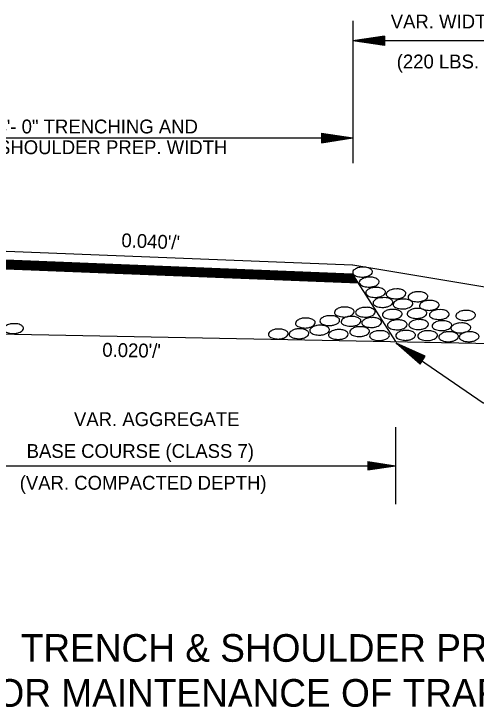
# Model space of a CAD drawing. Extents: x 1929624 to 1936506, y 596315 to 605721.
# Drawn here: x 1933894.6 to 1934095, y 603512.5 to 603813.2 of the extents above; entities that cross this region are included whole.
import ezdxf

# ---------------------------------------------------------------- set-up
doc = ezdxf.new("R2010")
doc.units = 0
doc.layers.add('Default', color=7, linetype='Continuous')
doc.layers.add('R_Border', color=7, linetype='Continuous')

msp = doc.modelspace()

# ---------------------------------------------------------------- linework, layer by layer
at = {"layer": 'Default'}
for p, q in [((1934041.58, 603810.24), (1934041.58, 603748.47)), ((1934055.28, 603803.61), (1934041.58, 603801.57)), ((1934055.28, 603803.28), (1934043.85, 603801.57)), ((1934055.28, 603803.61), (1934055.28, 603799.51)), ((1934055.28, 603799.51), (1934041.58, 603801.57)), ((1934282.32, 603801.57), (1934041.58, 603801.57)), ((1934055.28, 603799.86), (1934043.85, 603801.57)), ((1934055.28, 603802.93), (1934046.22, 603801.57)), ((1934055.28, 603800.2), (1934046.22, 603801.57)), ((1934055.28, 603802.6), (1934048.5, 603801.57)), ((1934055.28, 603800.56), (1934048.5, 603801.57)), ((1934055.28, 603802.21), (1934050.82, 603801.57)), ((1934055.28, 603800.89), (1934050.82, 603801.57)), ((1934055.28, 603801.9), (1934053.09, 603801.57)), ((1934055.28, 603801.24), (1934053.09, 603801.57)), ((1934027.9, 603761.42), (1934041.58, 603759.38)), ((1934027.9, 603761.42), (1934027.9, 603757.32)), ((1934027.9, 603761.09), (1934039.29, 603759.38)), ((1933862.89, 603759.38), (1934041.58, 603759.38)), ((1934027.9, 603760.73), (1934036.95, 603759.38)), ((1934027.9, 603760.4), (1934034.68, 603759.38)), ((1934027.9, 603760.03), (1934032.32, 603759.38)), ((1934027.9, 603759.7), (1934030.05, 603759.38)), ((1934027.9, 603757.32), (1934041.58, 603759.38)), ((1934027.9, 603758.69), (1934032.32, 603759.38)), ((1934027.9, 603758), (1934036.95, 603759.38)), ((1934027.9, 603757.66), (1934039.29, 603759.38)), ((1934027.9, 603758.36), (1934034.68, 603759.38)), ((1934027.9, 603759.05), (1934030.05, 603759.38)), ((1934041.58, 603755.33), (1934041.58, 603748.47)), ((1933859.07, 603711.63), (1934041.46, 603704.32)), ((1933859.07, 603707.83), (1934041.3, 603700.5)), ((1933859.07, 603707.39), (1934041.58, 603700.05)), ((1933859.07, 603707.06), (1934041.77, 603699.76)), ((1933859.07, 603706.64), (1934042.08, 603699.3)), ((1933859.07, 603706.22), (1934042.3, 603698.9)), ((1933859.07, 603705.86), (1934042.58, 603698.46)), ((1933859.07, 603705.48), (1934042.8, 603698.12)), ((1933859.07, 603705.1), (1934043.12, 603697.68)), ((1933859.07, 603704.68), (1934043.36, 603697.28)), ((1933859.07, 603704.31), (1934043.62, 603696.84)), ((1933859.07, 603703.98), (1934043.79, 603696.56)), ((1934041.58, 603704.32), (1934432.81, 603639.11)), ((1934041.3, 603700.5), (1934060, 603671.04)), ((1933862.98, 603674.97), (1934265.9, 603666.92)), ((1934070.71, 603661.22), (1934060.36, 603670.42)), ((1934072.95, 603664.68), (1934060.36, 603670.42)), ((1934070.9, 603661.49), (1934062.29, 603669.18)), ((1934072.78, 603664.36), (1934062.29, 603669.18)), ((1934072.58, 603664.09), (1934064.27, 603667.88)), ((1934071.1, 603661.8), (1934064.27, 603667.88)), ((1934071.29, 603662.09), (1934066.17, 603666.63)), ((1934072.39, 603663.78), (1934066.17, 603666.63)), ((1934072.2, 603663.5), (1934068.12, 603665.38)), ((1934071.47, 603662.4), (1934068.12, 603665.38)), ((1934070.71, 603661.22), (1934072.95, 603664.68)), ((1934072.01, 603663.2), (1934070.03, 603664.14)), ((1934071.67, 603662.66), (1934070.03, 603664.14)), ((1934060, 603633.89), (1934060, 603600.53)), ((1933862.98, 603617.21), (1934060, 603617.21)), ((1934048, 603619.01), (1934060, 603617.21)), ((1934048, 603619.01), (1934048, 603615.41)), ((1934048, 603618.71), (1934058, 603617.21)), ((1934048, 603618.4), (1934055.93, 603617.21)), ((1934048, 603618.1), (1934053.93, 603617.21)), ((1934048, 603617.79), (1934051.9, 603617.21)), ((1934048, 603617.49), (1934049.9, 603617.21)), ((1934048, 603615.41), (1934060, 603617.21)), ((1934048, 603616.62), (1934051.9, 603617.21)), ((1934048, 603616.02), (1934055.93, 603617.21)), ((1934048, 603615.71), (1934058, 603617.21)), ((1934048, 603616.32), (1934053.93, 603617.21)), ((1934048, 603616.93), (1934049.9, 603617.21))]:
    msp.add_line(p, q, dxfattribs=at)
for points in [[(1934045.68, 603703.29), (1934047.21, 603703.28), (1934049.03, 603702.64), (1934049.92, 603701.81), (1934050.04, 603701.27), (1934049.58, 603700.35), (1934049.06, 603699.96), (1934048.06, 603699.44), (1934046.6, 603699.1), (1934045.84, 603699.02), (1934044.73, 603699.13), (1934043.47, 603699.34), (1934042.52, 603699.71), (1934041.64, 603700.44), (1934041.49, 603701.02), (1934041.75, 603701.84), (1934042.45, 603702.37), (1934043.09, 603702.79), (1934044.11, 603703.14), (1934044.74, 603703.28), (1934045.68, 603703.29)], [(1934048.56, 603698.96), (1934050.06, 603698.95), (1934051.88, 603698.31), (1934052.8, 603697.47), (1934052.93, 603696.94), (1934052.44, 603696.02), (1934051.9, 603695.6), (1934050.95, 603695.1), (1934049.43, 603694.79), (1934048.7, 603694.68), (1934047.56, 603694.8), (1934046.35, 603695), (1934045.41, 603695.39), (1934044.51, 603696.08), (1934044.35, 603696.69), (1934044.64, 603697.5), (1934045.32, 603698.06), (1934045.98, 603698.48), (1934046.96, 603698.79), (1934047.58, 603698.95), (1934048.56, 603698.96)], [(1934051.32, 603694.49), (1934052.83, 603694.47), (1934054.64, 603693.85), (1934055.54, 603692.98), (1934055.7, 603692.48), (1934055.22, 603691.54), (1934054.69, 603691.12), (1934053.7, 603690.67), (1934052.22, 603690.28), (1934051.46, 603690.22), (1934050.34, 603690.3), (1934049.11, 603690.52), (1934048.16, 603690.9), (1934047.28, 603691.61), (1934047.13, 603692.21), (1934047.39, 603693.01), (1934048.08, 603693.59), (1934048.72, 603694.02), (1934049.75, 603694.33), (1934050.37, 603694.47), (1934051.32, 603694.49)], [(1934060.22, 603693.87), (1934061.73, 603693.85), (1934063.54, 603693.23), (1934064.46, 603692.35), (1934064.57, 603691.87), (1934064.11, 603690.92), (1934063.58, 603690.52), (1934062.6, 603690.03), (1934061.11, 603689.66), (1934060.36, 603689.6), (1934059.24, 603689.71), (1934058.01, 603689.91), (1934057.04, 603690.28), (1934056.17, 603691.01), (1934056.01, 603691.59), (1934056.28, 603692.4), (1934056.98, 603692.96), (1934057.62, 603693.38), (1934058.64, 603693.71), (1934059.25, 603693.85), (1934060.22, 603693.87)], [(1934069.68, 603692.6), (1934071.19, 603692.59), (1934073.03, 603691.98), (1934073.92, 603691.11), (1934074.06, 603690.62), (1934073.57, 603689.66), (1934073.04, 603689.25), (1934072.05, 603688.8), (1934070.57, 603688.43), (1934069.83, 603688.36), (1934068.7, 603688.44), (1934067.46, 603688.65), (1934066.53, 603689.03), (1934065.61, 603689.75), (1934065.5, 603690.33), (1934065.77, 603691.14), (1934066.44, 603691.7), (1934067.09, 603692.14), (1934068.09, 603692.46), (1934068.73, 603692.59), (1934069.68, 603692.6)], [(1934054.53, 603690.11), (1934056.01, 603690.09), (1934057.85, 603689.5), (1934058.72, 603688.63), (1934058.88, 603688.13), (1934058.41, 603687.18), (1934057.87, 603686.78), (1934056.88, 603686.31), (1934055.42, 603685.93), (1934054.64, 603685.87), (1934053.53, 603685.95), (1934052.3, 603686.15), (1934051.35, 603686.56), (1934050.45, 603687.27), (1934050.32, 603687.84), (1934050.59, 603688.66), (1934051.27, 603689.21), (1934051.9, 603689.64), (1934052.93, 603689.99), (1934053.55, 603690.09), (1934054.53, 603690.11)], [(1934063.24, 603689.47), (1934064.72, 603689.46), (1934066.56, 603688.83), (1934067.43, 603687.96), (1934067.59, 603687.46), (1934067.12, 603686.53), (1934066.58, 603686.12), (1934065.59, 603685.64), (1934064.13, 603685.26), (1934063.35, 603685.22), (1934062.26, 603685.28), (1934061.01, 603685.48), (1934060.06, 603685.89), (1934059.17, 603686.59), (1934059.03, 603687.18), (1934059.31, 603688.01), (1934060, 603688.57), (1934060.61, 603689), (1934061.64, 603689.3), (1934062.28, 603689.46), (1934063.24, 603689.47)], [(1934074.65, 603688.86), (1934076.14, 603688.85), (1934077.95, 603688.22), (1934078.86, 603687.35), (1934079.01, 603686.87), (1934078.53, 603685.93), (1934077.98, 603685.5), (1934077, 603685.05), (1934075.52, 603684.69), (1934074.77, 603684.61), (1934073.68, 603684.7), (1934072.42, 603684.91), (1934071.48, 603685.28), (1934070.57, 603685.98), (1934070.44, 603686.59), (1934070.72, 603687.41), (1934071.41, 603687.96), (1934072.03, 603688.4), (1934073.04, 603688.69), (1934073.7, 603688.85), (1934074.65, 603688.86)], [(1934037.8, 603686), (1934039.33, 603685.99), (1934041.15, 603685.35), (1934042.04, 603684.52), (1934042.16, 603683.98), (1934041.7, 603683.06), (1934041.18, 603682.67), (1934040.18, 603682.15), (1934038.72, 603681.81), (1934037.96, 603681.73), (1934036.85, 603681.84), (1934035.59, 603682.05), (1934034.64, 603682.42), (1934033.76, 603683.15), (1934033.61, 603683.73), (1934033.87, 603684.55), (1934034.57, 603685.08), (1934035.21, 603685.5), (1934036.23, 603685.85), (1934036.86, 603685.99), (1934037.8, 603686)], [(1934046.93, 603685.9), (1934048.46, 603685.89), (1934050.28, 603685.25), (1934051.17, 603684.42), (1934051.29, 603683.88), (1934050.83, 603682.96), (1934050.31, 603682.57), (1934049.31, 603682.05), (1934047.85, 603681.71), (1934047.09, 603681.63), (1934045.98, 603681.74), (1934044.72, 603681.95), (1934043.77, 603682.32), (1934042.89, 603683.05), (1934042.74, 603683.63), (1934043, 603684.45), (1934043.7, 603684.98), (1934044.34, 603685.4), (1934045.36, 603685.75), (1934045.99, 603685.89), (1934046.93, 603685.9)], [(1934058.55, 603685.01), (1934060.09, 603684.97), (1934061.92, 603684.36), (1934062.81, 603683.49), (1934062.91, 603682.99), (1934062.45, 603682.04), (1934061.93, 603681.63), (1934060.95, 603681.15), (1934059.47, 603680.79), (1934058.71, 603680.73), (1934057.6, 603680.82), (1934056.38, 603681.04), (1934055.42, 603681.41), (1934054.53, 603682.12), (1934054.37, 603682.72), (1934054.64, 603683.55), (1934055.33, 603684.08), (1934055.98, 603684.52), (1934056.98, 603684.84), (1934057.62, 603684.97), (1934058.55, 603685.01)], [(1934069.29, 603685.39), (1934070.8, 603685.37), (1934072.62, 603684.73), (1934073.54, 603683.88), (1934073.68, 603683.38), (1934073.18, 603682.44), (1934072.65, 603682.02), (1934071.69, 603681.54), (1934070.18, 603681.17), (1934069.44, 603681.12), (1934068.31, 603681.2), (1934067.09, 603681.41), (1934066.14, 603681.8), (1934065.25, 603682.51), (1934065.11, 603683.13), (1934065.38, 603683.91), (1934066.06, 603684.47), (1934066.72, 603684.91), (1934067.7, 603685.23), (1934068.32, 603685.37), (1934069.29, 603685.39)], [(1934078.95, 603684.91), (1934080.43, 603684.89), (1934082.27, 603684.27), (1934083.16, 603683.39), (1934083.31, 603682.88), (1934082.81, 603681.98), (1934082.28, 603681.54), (1934081.3, 603681.09), (1934079.81, 603680.7), (1934079.06, 603680.65), (1934077.94, 603680.73), (1934076.72, 603680.93), (1934075.77, 603681.32), (1934074.87, 603682.02), (1934074.73, 603682.63), (1934075.01, 603683.43), (1934075.68, 603684), (1934076.33, 603684.44), (1934077.34, 603684.73), (1934077.95, 603684.89), (1934078.95, 603684.91)], [(1934090.4, 603684.52), (1934091.91, 603684.5), (1934093.75, 603683.88), (1934094.63, 603683), (1934094.75, 603682.51), (1934094.3, 603681.59), (1934093.77, 603681.15), (1934092.77, 603680.68), (1934091.29, 603680.32), (1934090.56, 603680.25), (1934089.42, 603680.34), (1934088.17, 603680.54), (1934087.25, 603680.93), (1934086.34, 603681.63), (1934086.21, 603682.23), (1934086.49, 603683.05), (1934087.16, 603683.6), (1934087.8, 603684.05), (1934088.81, 603684.36), (1934089.45, 603684.5), (1934090.4, 603684.52)], [(1934020.9, 603681.23), (1934022.43, 603681.22), (1934024.25, 603680.58), (1934025.14, 603679.75), (1934025.26, 603679.21), (1934024.8, 603678.29), (1934024.28, 603677.9), (1934023.28, 603677.38), (1934021.82, 603677.04), (1934021.06, 603676.96), (1934019.95, 603677.07), (1934018.69, 603677.28), (1934017.74, 603677.65), (1934016.86, 603678.38), (1934016.71, 603678.96), (1934016.97, 603679.78), (1934017.67, 603680.31), (1934018.31, 603680.73), (1934019.33, 603681.08), (1934019.96, 603681.22), (1934020.9, 603681.23)], [(1934031.47, 603682.27), (1934033, 603682.26), (1934034.82, 603681.62), (1934035.71, 603680.79), (1934035.83, 603680.25), (1934035.37, 603679.33), (1934034.85, 603678.94), (1934033.85, 603678.42), (1934032.39, 603678.08), (1934031.63, 603678), (1934030.52, 603678.11), (1934029.26, 603678.32), (1934028.31, 603678.69), (1934027.43, 603679.42), (1934027.28, 603680), (1934027.54, 603680.82), (1934028.24, 603681.35), (1934028.88, 603681.77), (1934029.9, 603682.12), (1934030.53, 603682.26), (1934031.47, 603682.27)], [(1934040.7, 603681.96), (1934042.23, 603681.95), (1934044.05, 603681.31), (1934044.94, 603680.48), (1934045.06, 603679.94), (1934044.6, 603679.02), (1934044.08, 603678.63), (1934043.08, 603678.11), (1934041.62, 603677.77), (1934040.86, 603677.69), (1934039.75, 603677.8), (1934038.49, 603678.01), (1934037.54, 603678.38), (1934036.66, 603679.11), (1934036.51, 603679.69), (1934036.77, 603680.51), (1934037.47, 603681.04), (1934038.11, 603681.46), (1934039.13, 603681.81), (1934039.76, 603681.95), (1934040.7, 603681.96)], [(1934049.62, 603681.44), (1934051.15, 603681.43), (1934052.97, 603680.79), (1934053.86, 603679.96), (1934053.98, 603679.42), (1934053.52, 603678.5), (1934053, 603678.11), (1934052, 603677.59), (1934050.54, 603677.25), (1934049.78, 603677.17), (1934048.67, 603677.28), (1934047.41, 603677.49), (1934046.46, 603677.86), (1934045.58, 603678.59), (1934045.43, 603679.17), (1934045.69, 603679.99), (1934046.39, 603680.52), (1934047.03, 603680.94), (1934048.05, 603681.29), (1934048.68, 603681.43), (1934049.62, 603681.44)], [(1934060.72, 603680.45), (1934062.26, 603680.4), (1934064.08, 603679.79), (1934064.97, 603678.92), (1934065.08, 603678.42), (1934064.61, 603677.47), (1934064.1, 603677.07), (1934063.12, 603676.58), (1934061.64, 603676.23), (1934060.87, 603676.16), (1934059.77, 603676.26), (1934058.55, 603676.48), (1934057.58, 603676.85), (1934056.7, 603677.55), (1934056.54, 603678.16), (1934056.81, 603678.98), (1934057.49, 603679.51), (1934058.15, 603679.95), (1934059.14, 603680.28), (1934059.78, 603680.4), (1934060.72, 603680.45)], [(1934070, 603680.57), (1934071.52, 603680.56), (1934073.34, 603679.92), (1934074.26, 603679.06), (1934074.4, 603678.56), (1934073.9, 603677.63), (1934073.37, 603677.21), (1934072.4, 603676.72), (1934070.89, 603676.35), (1934070.16, 603676.3), (1934069.02, 603676.38), (1934067.81, 603676.6), (1934066.86, 603676.99), (1934065.97, 603677.69), (1934065.83, 603678.31), (1934066.09, 603679.09), (1934066.78, 603679.65), (1934067.43, 603680.09), (1934068.41, 603680.42), (1934069.04, 603680.56), (1934070, 603680.57)], [(1934080.1, 603680.09), (1934081.61, 603680.07), (1934083.44, 603679.44), (1934084.36, 603678.58), (1934084.5, 603678.08), (1934084, 603677.15), (1934083.47, 603676.72), (1934082.5, 603676.24), (1934080.99, 603675.87), (1934080.26, 603675.82), (1934079.12, 603675.9), (1934077.91, 603676.12), (1934076.95, 603676.51), (1934076.07, 603677.21), (1934075.93, 603677.83), (1934076.19, 603678.61), (1934076.88, 603679.17), (1934077.53, 603679.61), (1934078.51, 603679.93), (1934079.14, 603680.07), (1934080.1, 603680.09)], [(1933894.39, 603678.8), (1933895.92, 603678.79), (1933897.74, 603678.15), (1933898.63, 603677.32), (1933898.75, 603676.78), (1933898.29, 603675.86), (1933897.77, 603675.47), (1933896.77, 603674.95), (1933895.31, 603674.61), (1933894.55, 603674.53), (1933893.44, 603674.64), (1933892.18, 603674.85), (1933891.23, 603675.22), (1933890.35, 603675.95), (1933890.2, 603676.53), (1933890.46, 603677.35), (1933891.16, 603677.88), (1933891.8, 603678.3), (1933892.82, 603678.65), (1933893.45, 603678.79), (1933894.39, 603678.8)], [(1934027.07, 603678.12), (1934028.6, 603678.11), (1934030.42, 603677.47), (1934031.31, 603676.64), (1934031.43, 603676.1), (1934030.97, 603675.18), (1934030.45, 603674.79), (1934029.45, 603674.27), (1934027.99, 603673.93), (1934027.23, 603673.85), (1934026.12, 603673.96), (1934024.86, 603674.17), (1934023.91, 603674.54), (1934023.03, 603675.27), (1934022.88, 603675.85), (1934023.14, 603676.67), (1934023.84, 603677.2), (1934024.48, 603677.62), (1934025.5, 603677.97), (1934026.13, 603678.11), (1934027.07, 603678.12)], [(1934044.42, 603677.49), (1934045.95, 603677.48), (1934047.77, 603676.84), (1934048.66, 603676.01), (1934048.78, 603675.47), (1934048.32, 603674.55), (1934047.8, 603674.16), (1934046.8, 603673.64), (1934045.34, 603673.3), (1934044.58, 603673.22), (1934043.47, 603673.33), (1934042.21, 603673.54), (1934041.26, 603673.91), (1934040.38, 603674.64), (1934040.23, 603675.22), (1934040.49, 603676.04), (1934041.19, 603676.57), (1934041.83, 603676.99), (1934042.85, 603677.34), (1934043.48, 603677.48), (1934044.42, 603677.49)], [(1934088.27, 603679.12), (1934089.78, 603679.11), (1934091.6, 603678.47), (1934092.52, 603677.61), (1934092.66, 603677.11), (1934092.16, 603676.18), (1934091.63, 603675.76), (1934090.67, 603675.28), (1934089.16, 603674.9), (1934088.42, 603674.85), (1934087.29, 603674.93), (1934086.07, 603675.15), (1934085.12, 603675.54), (1934084.23, 603676.24), (1934084.09, 603676.86), (1934084.36, 603677.64), (1934085.04, 603678.2), (1934085.7, 603678.64), (1934086.68, 603678.97), (1934087.3, 603679.11), (1934088.27, 603679.12)], [(1934009.18, 603676.46), (1934010.71, 603676.45), (1934012.53, 603675.81), (1934013.42, 603674.98), (1934013.54, 603674.44), (1934013.08, 603673.52), (1934012.56, 603673.13), (1934011.56, 603672.61), (1934010.1, 603672.27), (1934009.34, 603672.19), (1934008.23, 603672.3), (1934006.97, 603672.51), (1934006.02, 603672.88), (1934005.14, 603673.61), (1934004.99, 603674.19), (1934005.25, 603675.01), (1934005.95, 603675.54), (1934006.59, 603675.96), (1934007.61, 603676.31), (1934008.24, 603676.45), (1934009.18, 603676.46)], [(1934018.16, 603676.56), (1934019.69, 603676.55), (1934021.51, 603675.91), (1934022.4, 603675.08), (1934022.52, 603674.54), (1934022.06, 603673.62), (1934021.54, 603673.23), (1934020.54, 603672.71), (1934019.08, 603672.37), (1934018.32, 603672.29), (1934017.21, 603672.4), (1934015.95, 603672.61), (1934015, 603672.98), (1934014.12, 603673.71), (1934013.97, 603674.29), (1934014.23, 603675.11), (1934014.93, 603675.64), (1934015.57, 603676.06), (1934016.59, 603676.41), (1934017.22, 603676.55), (1934018.16, 603676.56)], [(1934035.2, 603676.24), (1934036.73, 603676.23), (1934038.55, 603675.59), (1934039.44, 603674.76), (1934039.56, 603674.22), (1934039.1, 603673.3), (1934038.58, 603672.91), (1934037.58, 603672.39), (1934036.12, 603672.05), (1934035.36, 603671.97), (1934034.25, 603672.08), (1934032.99, 603672.29), (1934032.04, 603672.66), (1934031.16, 603673.39), (1934031.01, 603673.97), (1934031.27, 603674.79), (1934031.97, 603675.32), (1934032.61, 603675.74), (1934033.63, 603676.09), (1934034.26, 603676.23), (1934035.2, 603676.24)], [(1934053.01, 603675.77), (1934054.54, 603675.76), (1934056.36, 603675.12), (1934057.25, 603674.29), (1934057.37, 603673.75), (1934056.91, 603672.83), (1934056.39, 603672.44), (1934055.39, 603671.92), (1934053.93, 603671.58), (1934053.17, 603671.5), (1934052.06, 603671.61), (1934050.8, 603671.82), (1934049.85, 603672.19), (1934048.97, 603672.92), (1934048.82, 603673.5), (1934049.08, 603674.32), (1934049.78, 603674.85), (1934050.42, 603675.27), (1934051.44, 603675.62), (1934052.07, 603675.76), (1934053.01, 603675.77)], [(1934064.32, 603675.88), (1934065.86, 603675.84), (1934067.68, 603675.23), (1934068.57, 603674.36), (1934068.68, 603673.86), (1934068.21, 603672.91), (1934067.7, 603672.5), (1934066.72, 603672.02), (1934065.24, 603671.66), (1934064.47, 603671.6), (1934063.37, 603671.69), (1934062.15, 603671.91), (1934061.18, 603672.28), (1934060.3, 603672.98), (1934060.14, 603673.59), (1934060.41, 603674.42), (1934061.09, 603674.95), (1934061.75, 603675.38), (1934062.74, 603675.71), (1934063.38, 603675.84), (1934064.32, 603675.88)], [(1934073.85, 603675.76), (1934075.37, 603675.74), (1934077.19, 603675.1), (1934078.11, 603674.25), (1934078.25, 603673.75), (1934077.75, 603672.81), (1934077.22, 603672.39), (1934076.25, 603671.91), (1934074.74, 603671.54), (1934074.01, 603671.49), (1934072.87, 603671.57), (1934071.66, 603671.78), (1934070.71, 603672.17), (1934069.82, 603672.88), (1934069.68, 603673.5), (1934069.94, 603674.28), (1934070.63, 603674.84), (1934071.28, 603675.28), (1934072.26, 603675.6), (1934072.89, 603675.74), (1934073.85, 603675.76)], [(1934082.99, 603675.28), (1934084.5, 603675.26), (1934086.32, 603674.62), (1934087.24, 603673.76), (1934087.38, 603673.26), (1934086.88, 603672.33), (1934086.35, 603671.91), (1934085.38, 603671.43), (1934083.87, 603671.05), (1934083.14, 603671.01), (1934082, 603671.08), (1934080.79, 603671.3), (1934079.84, 603671.69), (1934078.95, 603672.39), (1934078.81, 603673.02), (1934079.07, 603673.79), (1934079.76, 603674.36), (1934080.41, 603674.79), (1934081.4, 603675.12), (1934082.02, 603675.26), (1934082.99, 603675.28)], [(1934091.87, 603675.28), (1934093.38, 603675.26), (1934095.2, 603674.62), (1934096.12, 603673.76), (1934096.26, 603673.26), (1934095.76, 603672.33), (1934095.23, 603671.91), (1934094.27, 603671.43), (1934092.76, 603671.05), (1934092.02, 603671.01), (1934090.89, 603671.08), (1934089.67, 603671.3), (1934088.72, 603671.69), (1934087.83, 603672.39), (1934087.69, 603673.02), (1934087.96, 603673.79), (1934088.64, 603674.36), (1934089.3, 603674.79), (1934090.28, 603675.12), (1934090.9, 603675.26), (1934091.87, 603675.28)]]:
    msp.add_spline(points, degree=3, dxfattribs=at)
at = {"layer": 'R_Border'}
msp.add_lwpolyline([(1934060.36, 603670.42), (1934098.06, 603644.55), (1934121.81, 603644.55)], dxfattribs=at)

# ---------------------------------------------------------------- texts
at = {"layer": 'Default'}
for s, height, p in [('VAR. WIDTH ACHM SURFACE COURSE (1/2")', 6, (1934057.97, 603806.89)), ('(220 LBS. PER SQ. YD.) & TACK COAT', 6, (1934060.57, 603789.55)), ('* 4\'- 0" TRENCHING AND ', 6, (1933881.73, 603761.36)), ('SHOULDER PREP. WIDTH ', 6, (1933887.73, 603752.36)), ('VAR. AGGREGATE', 6, (1933920.66, 603634.41)), ('BASE COURSE (CLASS 7)', 6, (1933900.14, 603620.62)), ('(VAR. COMPACTED DEPTH)', 6, (1933897.14, 603606.83)), ('TRENCH & SHOULDER PREP.', 12, (1933897.59, 603532.19)), ('FOR MAINTENANCE OF TRAFFIC', 12, (1933876.83, 603512.69))]:
    msp.add_text(s, height=height, dxfattribs=at).set_placement(p)
for s, rotation, p in [("0.040'/'", 357.7077, (1933941.12, 603712.05)), ("0.020'/'", 358.8543, (1933932.89, 603664.54))]:
    msp.add_text(s, height=6, rotation=rotation, dxfattribs=at).set_placement(p)

doc.saveas('drawing.dxf')
